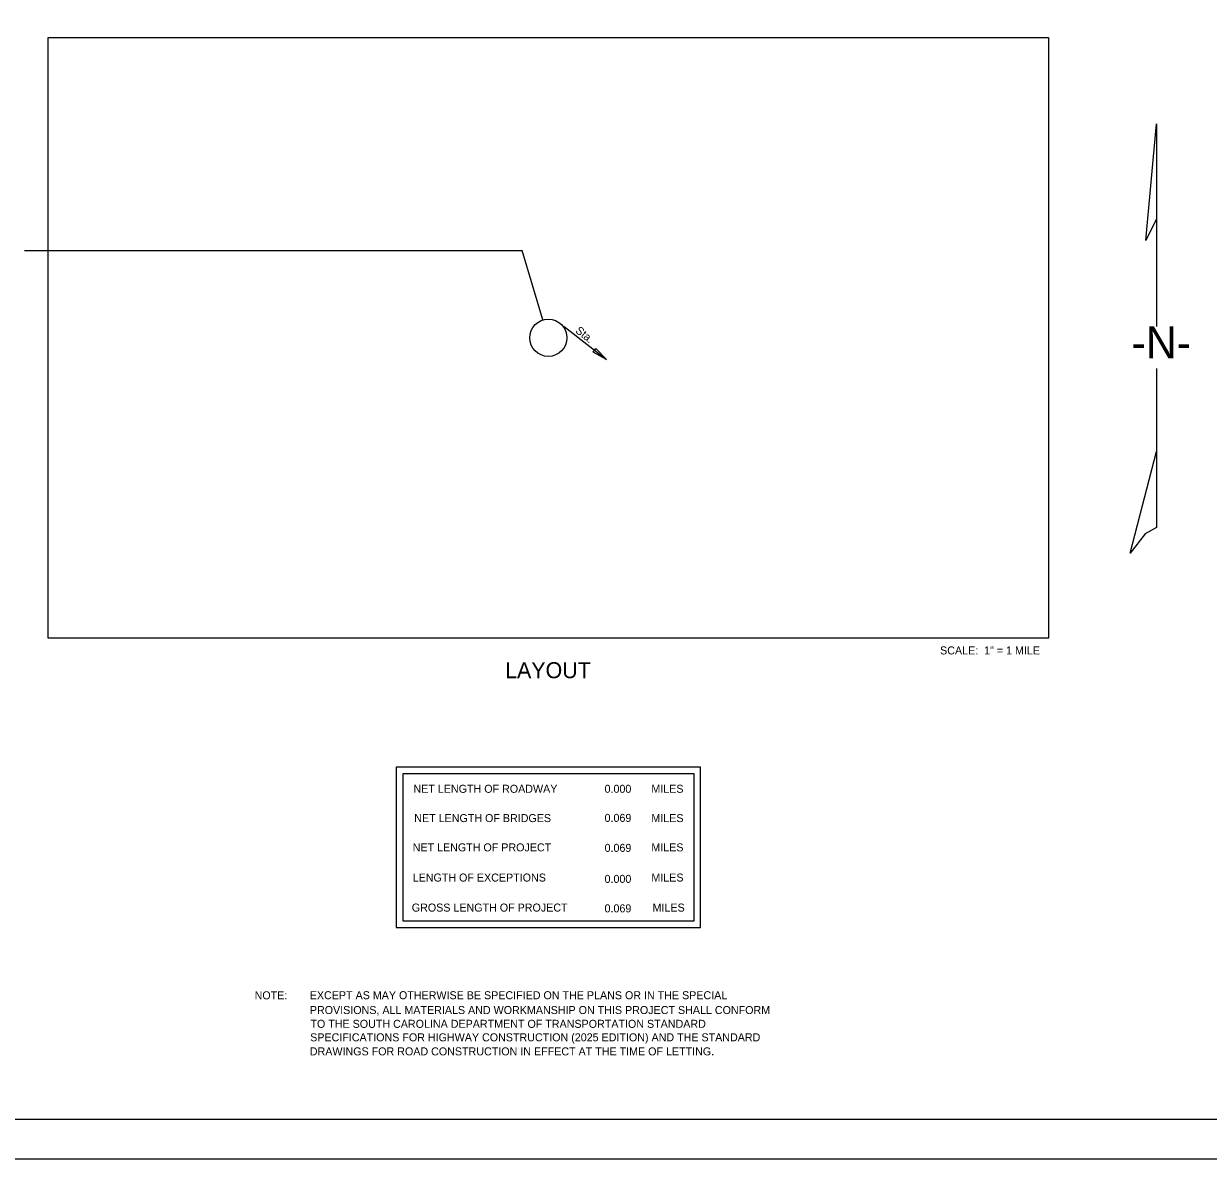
# Model space of a CAD drawing. Extents: x 291 to 2091, y 224 to 1324.
# Drawn here: x 892 to 1632, y 224 to 933 of the extents above; entities that cross this region are included whole.
import ezdxf

# ---------------------------------------------------------------- set-up
doc = ezdxf.new("R2010")
doc.units = 0
for name, color, linetype in [('BR_BORDER LINES', 7, 'Continuous'), ('BR_REBAR', 7, 'Continuous'), ('BR_TEXT', 7, 'Continuous'), ('Default', 7, 'Continuous'), ('RD_SHT_IplotShp', 7, 'Continuous')]:
    doc.layers.add(name, color=color, linetype=linetype)

msp = doc.modelspace()

# ---------------------------------------------------------------- linework, layer by layer
at = {"layer": 'BR_BORDER LINES'}
msp.add_line((391.1, 249.11), (2066.1, 249.11), dxfattribs=at)
at = {"layer": 'BR_REBAR'}
for p, q in [((906.87, 549.64), (906.87, 924.64)), ((906.87, 924.64), (1531.87, 924.64)), ((1531.87, 924.64), (1531.87, 549.64)), ((892.13, 791.71), (1202.92, 791.71)), ((1216.01, 748.27), (1202.92, 791.71)), ((1229.26, 744.2), (1255.62, 723.51)), ((1531.87, 549.64), (906.87, 549.64))]:
    msp.add_line(p, q, dxfattribs=at)
msp.add_lwpolyline([(1249.11, 730.4), (1255.62, 723.51), (1247.38, 728.19)], close=True, dxfattribs=at)
msp.add_circle((1219.37, 737.14), 11.62, dxfattribs=at)
at = {"layer": 'BR_TEXT'}
for points in [[(1314.37, 468.89), (1124.37, 468.89), (1124.37, 368.89), (1314.37, 368.89)], [(1310.37, 464.89), (1128.37, 464.89), (1128.37, 372.89), (1310.37, 372.89)]]:
    msp.add_lwpolyline(points, close=True, dxfattribs=at)
at = {"layer": 'Default'}
for p, q in [((906.87, 549.64), (906.87, 924.64)), ((906.87, 924.64), (1531.87, 924.64)), ((1531.87, 924.64), (1531.87, 549.64)), ((1592.64, 797.91), (1599.3, 870.7)), ((1599.3, 870.7), (1599.3, 811.42)), ((1599.3, 811.42), (1592.64, 797.91)), ((1599.3, 811.42), (1599.3, 770.33)), ((1599.3, 770.33), (1599.3, 744.13)), ((1599.3, 717.97), (1599.3, 666.17)), ((1582.8, 602.7), (1599.3, 666.17)), ((1599.3, 666.17), (1599.3, 658.33)), ((1599.3, 658.33), (1599.3, 618.64)), ((1531.87, 549.64), (906.87, 549.64))]:
    msp.add_line(p, q, dxfattribs=at)
msp.add_lwpolyline([(1599.3, 618.64), (1592.21, 614.76), (1582.8, 602.7)], dxfattribs=at)
at = {"layer": 'RD_SHT_IplotShp'}
msp.add_lwpolyline([(291.1, 1324.04), (2091.1, 1324.04), (2091.1, 224.04), (291.1, 224.04)], close=True, dxfattribs=at)

# ---------------------------------------------------------------- texts
at = {"layer": 'BR_REBAR'}
msp.add_text('Sta.', height=5, rotation=321.86505, dxfattribs=at).set_placement((1235.87, 740.83))
at = {"layer": 'BR_TEXT'}
for s, height, p in [('SCALE:  1" = 1 MILE', 5, (1464.11, 539.38)), ('LAYOUT', 10, (1192.37, 524.54)), ('NET LENGTH OF ROADWAY', 5, (1135.12, 452.97)), ('0.000', 5, (1254.49, 452.97)), ('MILES', 5, (1283.73, 452.97)), ('NET LENGTH OF BRIDGES', 5, (1135.62, 434.67)), ('0.069', 5, (1254.49, 434.79)), ('MILES', 5, (1283.72, 434.67)), ('NET LENGTH OF PROJECT', 5, (1134.62, 416.37)), ('0.069', 5, (1254.49, 416.06)), ('MILES', 5, (1283.72, 416.37)), ('LENGTH OF EXCEPTIONS', 5, (1134.62, 397.52)), ('0.000', 5, (1254.49, 396.69)), ('MILES', 5, (1283.74, 397.52)), ('GROSS LENGTH OF PROJECT', 5, (1134.07, 378.77)), ('0.069', 5, (1254.49, 378.28)), ('MILES', 5, (1284.49, 378.77)), ('NOTE:', 5, (1035.88, 323.96)), ('EXCEPT AS MAY OTHERWISE BE SPECIFIED ON THE PLANS OR IN THE SPECIAL ', 5.0001, (1070.33, 324.02)), ('PROVISIONS, ALL MATERIALS AND WORKMANSHIP ON THIS PROJECT SHALL CONFORM ', 5.0001, (1070.38, 314.77)), ('TO THE SOUTH CAROLINA DEPARTMENT OF TRANSPORTATION STANDARD ', 5.0001, (1070.74, 306.16)), ('SPECIFICATIONS FOR HIGHWAY CONSTRUCTION (2025 EDITION) AND THE STANDARD', 5.0001, (1070.59, 297.73)), ('DRAWINGS FOR ROAD CONSTRUCTION IN EFFECT AT THE TIME OF LETTING.', 5.0001, (1070.36, 288.95))]:
    msp.add_text(s, height=height, dxfattribs=at).set_placement(p)
at = {"layer": 'Default'}
msp.add_text('-N-', height=20, dxfattribs=at).set_placement((1583.73, 724.25))

doc.saveas('drawing.dxf')
